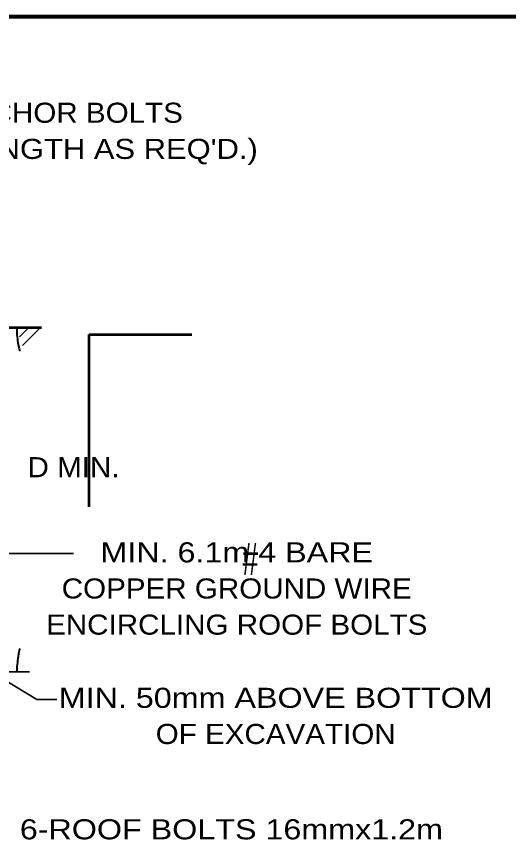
# Model space of a CAD drawing. Extents: x -39 to 816, y -16 to 528.
# Drawn here: x 490.2 to 563.5, y 397.8 to 521.9 of the extents above; entities that cross this region are included whole.
import ezdxf
from ezdxf.enums import TextEntityAlignment as Align

# ---------------------------------------------------------------- set-up
doc = ezdxf.new("R2010")
doc.units = 0
doc.header["$LTSCALE"] = 0.97
doc.layers.add('1', color=7, linetype='Continuous', lineweight=35)

msp = doc.modelspace()

# ---------------------------------------------------------------- linework, layer by layer
at = {"layer": '1'}
for p, q in [((491.9846, 475.3719), (490.6343, 474.0216)), ((493.6886, 475.3719), (491.0488, 472.7321)), ((478.7366, 423.9879), (492.1286, 423.9879))]:
    msp.add_line(p, q, dxfattribs=at)
at = {"layer": '1', "lineweight": 53}
for p, q in [((501.0288, 474.3609), (516.3168, 474.3609)), ((501.0288, 448.6449), (501.0288, 474.3609))]:
    msp.add_line(p, q, dxfattribs=at)
at = {"layer": '1', "lineweight": 158}
msp.add_lwpolyline([(809.7034, 521.852), (18.0034, 521.752), (18.1034, -4.248)], dxfattribs=at)
at = {"layer": '1', "lineweight": 53}
msp.add_lwpolyline([(419.0094, 475.3959), (444.4166, 475.3959), (444.4166, 473.7159), (447.7766, 477.0999), (447.7766, 475.3959), (464.9366, 475.3959), (464.9366, 473.7159), (468.2966, 477.0999), (468.2966, 475.4199), (493.9107, 475.4199)], dxfattribs=at)
at = {"layer": '1'}
for points in [[(473.0246, 427.2999), (486.5984, 441.6829), (498.6932, 441.6829)], [(483.5366, 425.6919), (493.1846, 419.8359), (496.2086, 419.8359)]]:
    msp.add_lwpolyline(points, dxfattribs=at)
at = {"layer": '1', "lineweight": 40}
for centre, major_axis, ratio, start_param, end_param in [((490.5244, 474.108), (-0.1889, 2.16), 0.122415, 0.89635335, 3.14159265), ((490.4462, 425.3374), (-0.2125, -2.1246), 0.07063, 3.14071475, 5.41810995), ((490.4462, 425.3374), (-0.2125, -2.1246), 0.07063, 3.14071475, 5.41810995)]:
    msp.add_ellipse(centre, major_axis=major_axis, ratio=ratio, start_param=start_param, end_param=end_param, dxfattribs=at)

# ---------------------------------------------------------------- texts
at = {"layer": '1'}
for s, width, p in [('ANCHOR BOLTS', 1.1, (480.1766, 505.9959)), ("(LENGTH AS REQ'D.)", 1.15, (480.1766, 500.5959)), ('D MIN.', 1.1, (491.8166, 453.0519))]:
    msp.add_text(s, height=3, dxfattribs=dict(at, width=width)).set_placement(p)
for s, height, width, p in [('MIN. 6.1m 4 BARE', 3, 1.2, (523.0252, 440.3376)), ('#', 4.8, 0.65, (525.0403, 438.4469)), ('COPPER GROUND WIRE', 3, 1.1, (523.0253, 434.9376)), ('ENCIRCLING ROOF BOLTS', 3, 1.1, (523.0252, 429.5376)), ('MIN. 50mm ABOVE BOTTOM', 3, 1.2, (528.8375, 418.609)), ('OF EXCAVATION', 3, 1.1, (528.8374, 413.209)), ('6-ROOF BOLTS 16mmx1.2m', 3, 1.2, (522.2286, 398.9668))]:
    msp.add_text(s, height=height, dxfattribs=dict(at, width=width)).set_placement(p, align=Align.CENTER)

doc.saveas('drawing.dxf')
